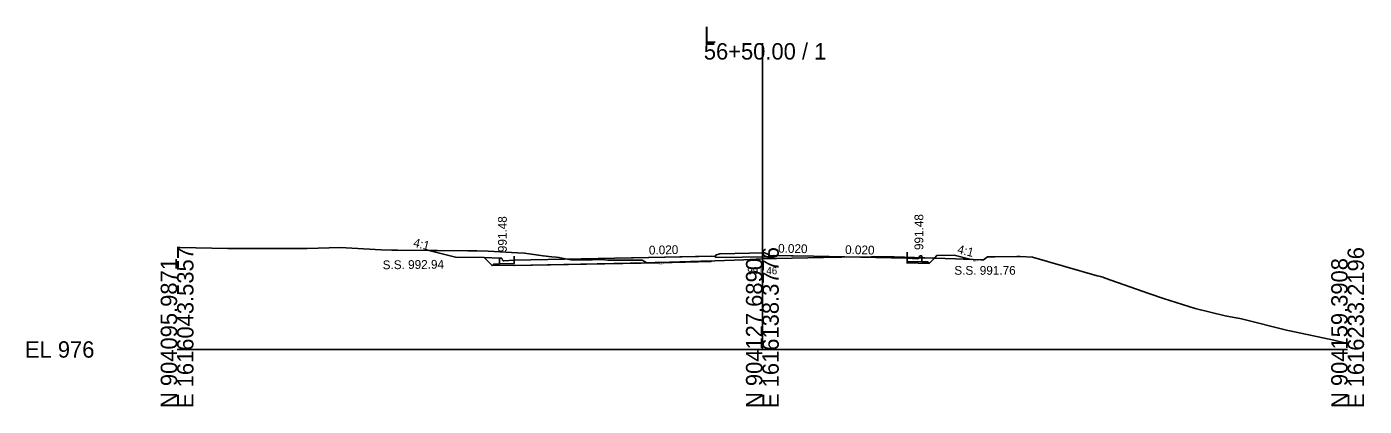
# Model space of a CAD drawing. Extents: x 1009 to 7438, y -1586 to 7964.
# Drawn here: x 5009.2 to 5237.7, y 4414 to 4478.8 of the extents above; entities that cross this region are included whole.
import ezdxf

# ---------------------------------------------------------------- set-up
doc = ezdxf.new("R2010")
doc.units = 0
for name, color, linetype in [('Exist Cross Section Cell', 7, 'Continuous'), ('Exist XS Center Line Elevation Label', 7, 'Continuous'), ('Exist XS Ground Line', 7, 'Continuous'), ('Prop XS Dump Level', 7, 'Continuous'), ('Prop XS Earthwork Shape', 7, 'Continuous'), ('Prop XS EOT Tick Mark', 7, 'Continuous'), ('Prop XS Finish Grade', 7, 'Continuous'), ('Prop XS Finish Grade CurbGutter', 7, 'Continuous'), ('Prop XS Finish Grade Earthwork', 7, 'Continuous'), ('Prop XS Finish Grade Pavement', 7, 'Continuous'), ('Prop XS Hydro Elevations', 7, 'Continuous'), ('Prop XS Pvmt Edge Slope', 7, 'Continuous'), ('Prop XS SE Text', 7, 'Continuous'), ('Prop XS Side Slope Text', 7, 'Continuous'), ('Prop XS SS Elevation Text', 7, 'Continuous'), ('Prop XS Subgrade CurbGutter', 7, 'Continuous'), ('Prop XS Subgrade Earthwork', 7, 'Continuous')]:
    doc.layers.add(name, color=color, linetype=linetype)

msp = doc.modelspace()

# ---------------------------------------------------------------- linework, layer by layer
at = {"layer": 'Exist Cross Section Cell'}
for p, q in [((5134.89, 4423.73), (5134.89, 4476.04)), ((5034.89, 4423.73), (5134.89, 4423.73)), ((5134.89, 4423.73), (5234.89, 4423.73))]:
    msp.add_line(p, q, dxfattribs=at)
at = {"layer": 'Exist XS Ground Line'}
for p, q in [((5034.89, 4441.17), (5035.36, 4441.16)), ((5035.36, 4441.16), (5043.53, 4440.96)), ((5043.53, 4440.96), (5043.93, 4440.96)), ((5043.93, 4440.96), (5044.59, 4440.96)), ((5044.59, 4440.96), (5054.04, 4440.98)), ((5054.04, 4440.98), (5054.79, 4440.98)), ((5054.79, 4440.98), (5057.09, 4440.98)), ((5057.09, 4440.98), (5062.76, 4441.13)), ((5062.76, 4441.13), (5069.75, 4440.75)), ((5069.75, 4440.75), (5071.56, 4440.71)), ((5071.56, 4440.71), (5072.52, 4440.71)), ((5072.52, 4440.71), (5079.41, 4440.63)), ((5079.41, 4440.63), (5084.58, 4440.59)), ((5084.58, 4440.59), (5086.1, 4440.57)), ((5086.1, 4440.57), (5088.03, 4440.53)), ((5088.03, 4440.53), (5093.06, 4440.25)), ((5093.06, 4440.25), (5094.26, 4440.17)), ((5094.26, 4440.17), (5097.44, 4439.71)), ((5097.44, 4439.71), (5098.89, 4439.56)), ((5098.89, 4439.56), (5099.64, 4439.49)), ((5099.64, 4439.49), (5100.14, 4439.44)), ((5100.14, 4439.44), (5100.64, 4439.35)), ((5100.64, 4439.35), (5102.24, 4439.06)), ((5102.24, 4439.06), (5103.53, 4439.03)), ((5103.53, 4439.03), (5105.09, 4438.97)), ((5105.09, 4438.97), (5106.53, 4439.07)), ((5106.53, 4439.07), (5107.47, 4439.07)), ((5107.47, 4439.07), (5108.48, 4438.97)), ((5108.48, 4438.97), (5111.63, 4438.96)), ((5111.63, 4438.96), (5114.04, 4438.99)), ((5114.04, 4438.99), (5114.35, 4438.98)), ((5114.35, 4438.98), (5115.15, 4438.52)), ((5115.15, 4438.52), (5116.6, 4438.57)), ((5116.6, 4438.57), (5117.23, 4438.59)), ((5117.23, 4438.59), (5126.76, 4438.89)), ((5126.76, 4438.89), (5131.72, 4439.06)), ((5131.72, 4439.06), (5134.89, 4439.19)), ((5134.89, 4439.19), (5137.3, 4439.28)), ((5137.3, 4439.28), (5145.36, 4439.45)), ((5145.36, 4439.45), (5148.46, 4439.52)), ((5148.46, 4439.52), (5153.48, 4439.57)), ((5153.48, 4439.57), (5154.03, 4439.58)), ((5154.03, 4439.58), (5155.37, 4439.55)), ((5155.37, 4439.55), (5157.39, 4439.54)), ((5157.39, 4439.54), (5167.89, 4439.2)), ((5167.89, 4439.2), (5170.9, 4439.08)), ((5170.9, 4439.08), (5172.23, 4439.06)), ((5172.23, 4439.06), (5172.69, 4439.05)), ((5172.69, 4439.05), (5173.35, 4439.53)), ((5173.35, 4439.53), (5174.63, 4439.56)), ((5174.63, 4439.56), (5178.38, 4439.63)), ((5178.38, 4439.63), (5178.96, 4439.61)), ((5178.96, 4439.61), (5181.03, 4439.52)), ((5181.03, 4439.52), (5192.12, 4436.33)), ((5192.12, 4436.33), (5192.67, 4436.17)), ((5192.67, 4436.17), (5193.04, 4436.06)), ((5193.04, 4436.06), (5193.48, 4435.9)), ((5193.48, 4435.9), (5200.94, 4433.28)), ((5200.94, 4433.28), (5203.44, 4432.41)), ((5203.44, 4432.41), (5208.85, 4430.71)), ((5208.85, 4430.71), (5213.99, 4429.45)), ((5213.99, 4429.45), (5216.75, 4428.94)), ((5216.75, 4428.94), (5224.65, 4426.99)), ((5224.65, 4426.99), (5225.02, 4426.91)), ((5225.02, 4426.91), (5232.56, 4425.3)), ((5232.56, 4425.3), (5234.89, 4424.75))]:
    msp.add_line(p, q, dxfattribs=at)
at = {"layer": 'Prop XS Dump Level'}
for p, q in [((5110.14, 4439.33), (5126.14, 4439.65)), ((5110.14, 4439.33), (5126.14, 4439.65)), ((5136.75, 4439.79), (5143.64, 4439.65)), ((5136.75, 4439.79), (5143.64, 4439.65)), ((5143.64, 4439.65), (5159.64, 4439.33)), ((5143.64, 4439.65), (5159.64, 4439.33))]:
    msp.add_line(p, q, dxfattribs=at)
at = {"layer": 'Prop XS Earthwork Shape'}
for points in [[(5092.47, 4438.97), (5090.72, 4438.87), (5090.59, 4438.89), (5090.5, 4438.98), (5090.43, 4439.23), (5090.34, 4439.33), (5090.22, 4439.35), (5089.97, 4439.35), (5087.38, 4439.41), (5082.47, 4439.51), (5077.93, 4440.65), (5079.41, 4440.63), (5084.58, 4440.59), (5086.1, 4440.57), (5088.03, 4440.53), (5093.06, 4440.25), (5094.26, 4440.17), (5097.44, 4439.71), (5098.89, 4439.56), (5099.64, 4439.49), (5100.14, 4439.44), (5100.64, 4439.35), (5102.24, 4439.06), (5103.53, 4439.03), (5105.09, 4438.97), (5106.53, 4439.07), (5107.47, 4439.07), (5108.48, 4438.97), (5111.63, 4438.96), (5114.04, 4438.99), (5114.35, 4438.98), (5115.15, 4438.52), (5092.47, 4438.06), (5092.47, 4438.14), (5088.72, 4438.07), (5088.97, 4438.32), (5089.97, 4438.34), (5092.47, 4438.39)], [(5089.97, 4438.34), (5089.97, 4439.35), (5087.38, 4439.41), (5088.72, 4438.07), (5088.97, 4438.32)], [(5092.47, 4438.97), (5090.72, 4438.87), (5090.59, 4438.89), (5090.5, 4438.98), (5090.43, 4439.23), (5090.34, 4439.33), (5090.22, 4439.35), (5089.97, 4439.35), (5089.97, 4438.34), (5092.47, 4438.39)], [(5115.15, 4438.52), (5116.6, 4438.57), (5117.23, 4438.59), (5117.25, 4438.59), (5117.25, 4438.55)], [(5117.25, 4438.59), (5126.14, 4438.88), (5126.14, 4438.73), (5117.25, 4438.55)], [(5161.52, 4439.25), (5161.61, 4439.34), (5161.63, 4439.4), (5159.64, 4439.46), (5159.64, 4439.33), (5161.39, 4439.22)], [(5161.63, 4439.4), (5162.14, 4439.38), (5162.14, 4438.7), (5159.64, 4438.75), (5159.64, 4439.33), (5161.39, 4439.22), (5161.52, 4439.25), (5161.61, 4439.34)], [(5163.14, 4438.68), (5163.39, 4438.42), (5159.64, 4438.5), (5159.64, 4438.75), (5162.14, 4438.7)], [(5163.14, 4438.68), (5163.39, 4438.42), (5164.28, 4439.31), (5162.14, 4439.38), (5162.14, 4438.7)], [(5164.28, 4439.31), (5167.89, 4439.2), (5170.55, 4439.1), (5167.64, 4439.82), (5164.73, 4439.76)]]:
    msp.add_lwpolyline(points, close=True, dxfattribs=at)
at = {"layer": 'Prop XS EOT Tick Mark'}
for p, q in [((5092.47, 4438.64), (5092.47, 4439.64)), ((5159.64, 4439.33), (5159.64, 4440.33))]:
    msp.add_line(p, q, dxfattribs=at)
at = {"layer": 'Prop XS Finish Grade'}
msp.add_line((5089.97, 4439.35), (5087.38, 4439.41), dxfattribs=at)
at = {"layer": 'Prop XS Finish Grade CurbGutter'}
for p, q in [((5089.97, 4439.35), (5090.22, 4439.35)), ((5090.22, 4439.35), (5090.34, 4439.33)), ((5090.43, 4439.23), (5090.34, 4439.33)), ((5090.5, 4438.98), (5090.43, 4439.23)), ((5090.59, 4438.89), (5090.5, 4438.98)), ((5090.72, 4438.87), (5090.59, 4438.89)), ((5092.47, 4438.97), (5090.72, 4438.87)), ((5126.89, 4439.83), (5127.64, 4440.08)), ((5126.89, 4439.66), (5126.89, 4439.83)), ((5127.64, 4440.08), (5135.25, 4440.21)), ((5136, 4439.97), (5135.25, 4440.21)), ((5136, 4439.8), (5136, 4439.97)), ((5159.64, 4439.33), (5161.39, 4439.22)), ((5161.39, 4439.22), (5161.52, 4439.25)), ((5161.52, 4439.25), (5161.61, 4439.34)), ((5161.61, 4439.34), (5161.68, 4439.59)), ((5161.68, 4439.59), (5161.77, 4439.68)), ((5161.89, 4439.71), (5161.77, 4439.68)), ((5162.14, 4439.71), (5161.89, 4439.71))]:
    msp.add_line(p, q, dxfattribs=at)
at = {"layer": 'Prop XS Finish Grade Earthwork'}
for p, q in [((5082.47, 4439.51), (5077.93, 4440.65)), ((5087.38, 4439.41), (5082.47, 4439.51)), ((5164.73, 4439.76), (5167.64, 4439.82)), ((5167.64, 4439.82), (5170.55, 4439.1))]:
    msp.add_line(p, q, dxfattribs=at)
at = {"layer": 'Prop XS Finish Grade Pavement'}
for p, q in [((5092.47, 4438.97), (5126.89, 4439.66)), ((5136, 4439.8), (5143.64, 4439.65)), ((5143.64, 4439.65), (5159.64, 4439.33))]:
    msp.add_line(p, q, dxfattribs=at)
at = {"layer": 'Prop XS Pvmt Edge Slope'}
for p, q in [((5088.97, 4438.32), (5088.72, 4438.07)), ((5089.97, 4438.34), (5088.97, 4438.32)), ((5162.14, 4438.7), (5163.14, 4438.68)), ((5163.14, 4438.68), (5163.39, 4438.42))]:
    msp.add_line(p, q, dxfattribs=at)
at = {"layer": 'Prop XS Subgrade CurbGutter'}
for p, q in [((5089.97, 4438.34), (5089.97, 4439.35)), ((5092.47, 4438.39), (5089.97, 4438.34)), ((5092.47, 4438.97), (5092.47, 4438.39)), ((5126.89, 4439.66), (5126.89, 4439.41)), ((5126.89, 4439.41), (5136, 4439.55)), ((5136, 4439.8), (5136, 4439.55)), ((5159.64, 4439.33), (5159.64, 4438.75)), ((5159.64, 4438.75), (5162.14, 4438.7)), ((5162.14, 4438.7), (5162.14, 4439.71))]:
    msp.add_line(p, q, dxfattribs=at)
at = {"layer": 'Prop XS Subgrade Earthwork'}
for p, q in [((5088.72, 4438.07), (5087.38, 4439.41)), ((5092.47, 4438.14), (5088.72, 4438.07)), ((5117.25, 4438.55), (5092.47, 4438.06)), ((5092.47, 4438.06), (5092.47, 4438.14)), ((5117.25, 4438.55), (5126.14, 4438.73)), ((5117.25, 4438.55), (5117.25, 4438.59)), ((5117.25, 4438.55), (5117.25, 4438.59)), ((5126.14, 4438.88), (5126.14, 4438.73)), ((5159.64, 4438.41), (5159.64, 4439.46)), ((5159.64, 4438.41), (5159.64, 4438.5)), ((5159.64, 4438.5), (5163.39, 4438.42)), ((5163.39, 4438.42), (5164.73, 4439.76))]:
    msp.add_line(p, q, dxfattribs=at)

# ---------------------------------------------------------------- texts
at = {"layer": 'Exist Cross Section Cell'}
for s, p in [('L', (5124.89, 4476.04)), ('56+50.00 / 1', (5124.89, 4473.24)), ('EL 976', (5008.89, 4422.33))]:
    msp.add_text(s, height=2.8, dxfattribs=at).set_placement(p)
for s, p in [('E 1616043.5357', (5037.69, 4413.73)), ('E 1616138.3776', (5137.69, 4413.73)), ('E 1616233.2196', (5237.69, 4413.73)), ('N 904095.9871', (5034.89, 4413.73)), ('N 904127.6890', (5134.89, 4413.73)), ('N 904159.3908', (5234.89, 4413.73))]:
    msp.add_text(s, height=2.8, rotation=90, dxfattribs=at).set_placement(p)
at = {"layer": 'Exist XS Center Line Elevation Label'}
msp.add_text('991.46', height=1.25, dxfattribs=at).set_placement((5132.31, 4436.56))
at = {"layer": 'Prop XS Dump Level'}
for p in [(5117.25, 4438.29), (5117.25, 4438.29), (5117.25, 4438.29), (5170.9, 4438.78)]:
    msp.add_text('Eop', height=0.3, dxfattribs=at).set_placement(p)
at = {"layer": 'Prop XS Hydro Elevations'}
for p in [(5091.22, 4440.35), (5162.39, 4440.71)]:
    msp.add_text('991.48', height=1.5, rotation=90, dxfattribs=at).set_placement(p)
at = {"layer": 'Prop XS SE Text'}
for rotation, p in [(1.1458, (5115.52, 4439.94)), (358.8542, (5137.57, 4440.27)), (358.8542, (5149.02, 4440.04))]:
    msp.add_text('0.020', height=1.5, rotation=rotation, dxfattribs=at).set_placement(p)
at = {"layer": 'Prop XS Side Slope Text'}
for p in [(5075.13, 4441.32), (5168.1, 4440.19)]:
    msp.add_text('4:1', height=1.5, rotation=345.9638, dxfattribs=at).set_placement(p)
at = {"layer": 'Prop XS SS Elevation Text'}
msp.add_text('S.S. 992.94', height=1.5, rotation=0.5729, dxfattribs=at).set_placement((5070.02, 4437.43))
msp.add_text('S.S. 991.76', height=1.5, dxfattribs=at).set_placement((5167.69, 4436.49))

doc.saveas('drawing.dxf')
